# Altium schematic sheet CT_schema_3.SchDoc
size 287 x 163 mm
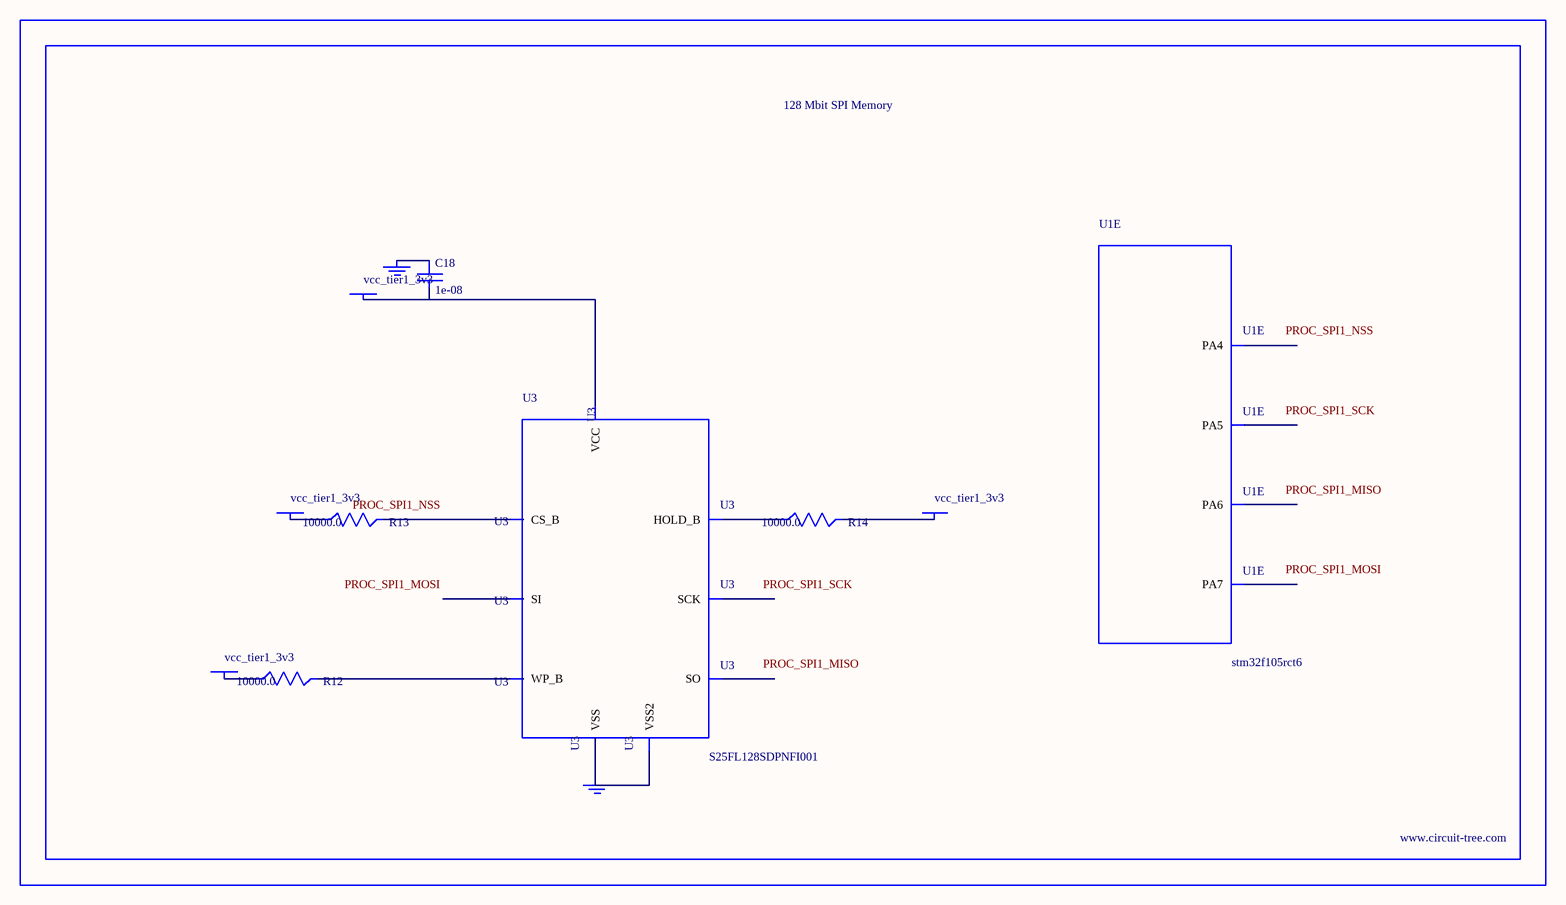
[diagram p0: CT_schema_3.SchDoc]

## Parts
BORDER2  (no value)
C18  1e-08  [C0402]
GND_INSTANCE_2_0  (no value)
GND_INSTANCE_2_1  (no value)
POWER_INSTANCE_2_0  vcc_tier1_3v3
POWER_INSTANCE_2_1  vcc_tier1_3v3
POWER_INSTANCE_2_2  vcc_tier1_3v3
POWER_INSTANCE_2_3  vcc_tier1_3v3
R12  10000.0  [R0603]
R13  10000.0  [R0603]
R14  10000.0  [R0603]
U1  stm32f105rct6  [LQFP64]  (part E of 7)
U3  S25FL128SDPNFI001  [WNG008]

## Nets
NetC18_1: C18.1 GND_INSTANCE_2_0.0(GND)
NetC18_2: C18.2 POWER_INSTANCE_2_3.0(PWR) U3.8(VCC)
NetGND_INSTANCE_2_1_0: GND_INSTANCE_2_1.0(GND) U3.4(VSS) U3.PAD(VSS2)
NetPOWER_INSTANCE_2_0_0: POWER_INSTANCE_2_0.0(PWR) R13.1
NetPOWER_INSTANCE_2_1_0: POWER_INSTANCE_2_1.0(PWR) R12.1
NetPOWER_INSTANCE_2_2_0: POWER_INSTANCE_2_2.0(PWR) R14.2
NetR12_2: R12.2 U3.3(WP_B)
NetR13_2: R13.2 U3.1(CS_B)
NetR14_1: R14.1 U3.7(HOLD_B)

Not connected (* = marked no-connect by the designer): U1 20(PA4) 21(PA5) 22(PA6) 23(PA7); U3 2(SO) 5(SI) 6(SCK)

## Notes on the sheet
- Labels drawn without touching a wire or pin: PROC_SPI1_MISO, PROC_SPI1_MOSI, PROC_SPI1_NSS, PROC_SPI1_SCK

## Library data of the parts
BORDER2 = BORDER_PAGE2
C18 = C0402C103K3RAC
GND_INSTANCE_2_0 GND_INSTANCE_2_1 = GND
POWER_INSTANCE_2_0-POWER_INSTANCE_2_3 = PWR
R12-R14 = RC0603JR-0710KL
